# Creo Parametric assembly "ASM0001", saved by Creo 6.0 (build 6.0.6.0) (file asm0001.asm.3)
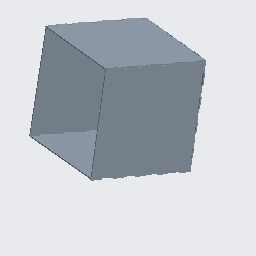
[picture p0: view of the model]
Units: Inch lbm Second (Pro/E Default); INCH, POUND, SECS

Created from: INLBS_ASM_DESIGN.ASM

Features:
  1. datum plane "ASM_RIGHT"
  2. datum plane "ASM_TOP"
  3. datum plane "ASM_FRONT"
  4. coordinate system
  5. component "PRT0001"
  6. component "LEFT"
  7. coordinate system
  8. component "BACK"
  9. component "PRT0002"
  10. component "RIGHT"

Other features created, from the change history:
  component "BACK.PRT"
  component "RIGHT.PRT"
  component "PRT0002.PRT"

Other named items: ACS4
